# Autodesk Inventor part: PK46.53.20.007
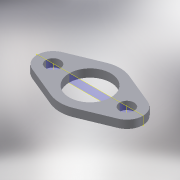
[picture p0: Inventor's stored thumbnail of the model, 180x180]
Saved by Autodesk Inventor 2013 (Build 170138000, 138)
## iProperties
Created: 2005-03
Part Number: PK46.53.20.007
Material: Steel, Mild
Document SubType Name: Modeling
Designer: HKostja
Manufacturer: Standard
Standards Organization: Custom
Density: 7.86 g/cm^3
Mass: 338.113 g
Surface Area: 145.993 cm^2
Volume: 43.0169 cm^3
Author: HKostja
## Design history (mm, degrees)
sketch "Эскиз1"
  geometry: L1 (-46, 0)-(46, 0); L2 (-53.609, 18.496)-(-14.266, 34.68); L3 (14.266, 34.68)-(53.609, 18.496); L4 (53.609, -18.496)-(14.266, -34.68); L5 (-14.266, -34.68)-(-53.609, -18.496); C1 r 26 at (0, 0); C2 r 9 at (-46, 0); C3 r 9 at (46, 0); A1 r 20 centre (-46, 0) between (-53.609, 18.496) and (-53.609, -18.496); A2 r 20 centre (46, 0) between (53.609, -18.496) and (53.609, 18.496); A3 r 37.5 centre (0, 0) between (-14.266, -34.68) and (14.266, -34.68); A4 r 37.5 centre (0, 0) between (14.266, 34.68) and (-14.266, 34.68); 1 further point
  constraints: 10 end point, 8 point on circle, 8 tangent, 7 centre point, 6 coincident, 3 equal radius, 1 horizontal, 1 midpoint, 1 other
  dimensions: "d0" = 52 diameter of C1; "d1" = 18 diameter of C2; "d2" = 92 distance of L1.end C2.centre; "d3" = 37.5 radius of A4; "d4" = 20 radius of A1
extrude "Выдавливание1" new body sketch "Эскиз1" distance "d5" = 10; taper "d6" = 0 deg
node "РабОсь1"
node "РабОсь2"
node "РабПлоскость1"
body "Solid1"
